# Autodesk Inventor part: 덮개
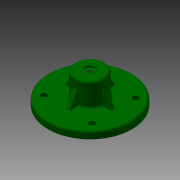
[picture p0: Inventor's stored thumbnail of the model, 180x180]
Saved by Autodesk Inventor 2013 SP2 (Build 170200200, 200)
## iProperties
Created: 2017-08
Part Number: 덮개
Material: 알루미늄 6061
Document SubType Name: Modeling
Designer: mduedu
Density: 2.71 g/cm^3
Mass: 358.12 g
Surface Area: 294.002 cm^2
Volume: 132.148 cm^3
Author: mduedu
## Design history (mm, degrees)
sketch "스케치1"
  geometry: C1 r 57.5 at (0, 0); 1 further point
  constraints: 1 centre point, 1 coincident
  dimensions: "d69" = 115 diameter of C1
extrude "돌출1" new body sketch "스케치1" distance "d5" = 10; taper "d6" = 0 deg
sketch "스케치2"
  geometry: C1 r 20 at (0, 0); 1 further point
  constraints: 1 centre point, 1 coincident
  dimensions: "d55" = 40 diameter of C1
extrude "돌출2" join sketch "스케치2" distance "d9" = 32; taper "d10" = 0 deg
sketch "스케치3"
  geometry: L1 (-26, -26)-(26, -26); L2 (26, -26)-(26, 26); L3 (26, 26)-(-26, 26); L4 (-26, 26)-(-26, -26); L5 (-26, -26)-(26, 26); L6 (26, -26)-(-26, 26); 1 further point
  constraints: 12 end point, 2 midpoint, 2 parallel, 2 perpendicular, 1 horizontal
  dimensions: "d11" = 52 distance of L3.end L2.end
extrude "돌출3" join sketch "스케치3" distance "d12" = 6; taper "d13" = 0 deg
sketch "스케치4"
  geometry: L1 (-17, -17)-(17, -17); L2 (17, -17)-(17, 17); L3 (17, 17)-(-17, 17); L4 (-17, 17)-(-17, -17); L5 (-17, -17)-(17, 17); L6 (17, -17)-(-17, 17); 1 further point
  constraints: 12 end point, 2 midpoint, 2 parallel, 2 perpendicular, 1 horizontal
  dimensions: "d14" = 34 distance of L2.end L3.end
extrude "돌출4" cut sketch "스케치4" distance "d16" = 5; taper "d17" = 0 deg
sketch "스케치5"
  geometry: C1 r 9 at (0, 0); 1 further point
  constraints: 1 centre point, 1 coincident
  dimensions: "d18" = 18 diameter of C1
extrude "돌출5" cut sketch "스케치5" distance "d19" = 34; taper "d20" = 0 deg
sketch "스케치6"
  geometry: 2 further points
  constraints: 1 coincident
hole "구멍1" sketch "스케치6" at (0, 0) diameter "d21" = 5.917; stored, may be unused: countersink angle "d25" = 90 deg, drill point angle "d27" = 118 deg; dims "d22" = 6, "d23" = 14, "d24" = 2, "d26" = 8
fillet "모깎기3" dims "d38" = 3
fillet "모깎기4" dims "d39" = 3
fillet "모깎기5" dims "d40" = 3
chamfer "모따기2" distance "d70" = 6; stored, may be unused: second distance "d71" = 2, angle "d72" = 45 deg
chamfer "모따기1" distance "d41" = 1; stored, may be unused: second distance "d42" = 2, angle "d43" = 45 deg
fillet "모깎기6" dims "d44" = 3
fillet "모깎기7" dims "d45" = 3
fillet "모깎기8" dims "d46" = 3
sketch "스케치9"
  geometry: L1 (-33, -30)-(33, -30); L2 (33, -30)-(33, 30); L3 (33, 30)-(-33, 30); L4 (-33, 30)-(-33, -30); L5 (-33, -30)-(33, 30); L6 (33, -30)-(-33, 30); C1 r 54.5 at (0, 0) reference; 3 further points
  constraints: 12 end point, 2 coincident, 2 midpoint, 2 parallel, 2 point on line, 1 horizontal, 1 perpendicular
  dimensions: "d77" = 66 distance of L2.end L3.end; "d79" = 60 distance of L1.end L2.end
hole "구멍3" sketch "스케치9" at (-33, -30), (-33, 30), (33, 30), (33, -30) diameter "d48" = 4.5; stored, may be unused: countersink angle "d52" = 90 deg, drill point angle "d54" = 0 deg; dims "d49" = 6, "d50" = 8, "d51" = 4.6, "d53" = 8
sketch "스케치10"
  geometry: L1 (-7, 40)-(-2.958, 40) reference; L2 (-2.958, 40)-(-2.958, 33) reference; L3 (-2.958, 33)-(-6, 33) reference; L4 (-9, 30)-(-9, -1) reference; L5 (-9, -1)-(-14, -1) reference; L6 (-17, -4)-(-17, -6) reference; L7 (-17, -6)-(-25, -6) reference; L8 (-25, -6)-(-26, -5) reference; L9 (-26, -5)-(-26, 0) reference; L10 (-26, 0)-(-57.5, 0) reference; L11 (-54.5, 10)-(-23, 10) reference; L12 (-20, 13)-(-20, 39) reference; L13 (-17, 42)-(-7, 42) reference; L14 (-7, 42)-(-7, 40) reference; L15 (2.958, 40)-(7, 40) reference; L16 (7, 40)-(7, 42) reference; L17 (7, 42)-(17, 42) reference; L18 (20, 39)-(20, 13) reference; L19 (23, 10)-(54.5, 10) reference; L20 (57.5, 0)-(26, 0) reference; L21 (26, 0)-(26, -5) reference; L22 (26, -5)-(25, -6) reference; L23 (25, -6)-(17, -6) reference; L24 (17, -6)-(17, -4) reference; L25 (14, -1)-(9, -1) reference; L26 (9, -1)-(9, 30) reference; L27 (6, 33)-(2.958, 33) reference; L28 (2.958, 33)-(2.958, 40) reference; L29 (31.547, 10)-(20, 30); L30 (-57.5, 0)-(-57.5, 7) reference; L31 (57.5, 7)-(57.5, 0) reference; A1 r 3 centre (-6, 30) between (-6, 33) and (-9, 30) reference; A2 r 3 centre (-14, -4) between (-14, -1) and (-17, -4) reference; A3 r 3 centre (-23, 13) between (-23, 10) and (-20, 13) reference; A4 r 3 centre (-17, 39) between (-17, 42) and (-20, 39) reference; A5 r 3 centre (17, 39) between (20, 39) and (17, 42) reference; A6 r 3 centre (23, 13) between (20, 13) and (23, 10) reference; A7 r 3 centre (14, -4) between (17, -4) and (14, -1) reference; A8 r 3 centre (6, 30) between (9, 30) and (6, 33) reference; A9 r 3 centre (-54.5, 7) between (-54.5, 10) and (-57.5, 7) reference; 2 further points
  constraints: 2 end point, 2 point on line, 1 other
  dimensions: "d56" = 20 distance from line of L29.end L19; "d57" = 120 deg angle of L29 L19
feature "리브1" sketch "스케치10" dims "d58" = 1, "d59" = 6, "d60" = 0, "d61" = 0, "d62" = 1, "d63" = 1
fillet "모깎기9" dims "d64" = 1
fillet "모깎기10" dims "d65" = 1
node "솔리드1"
pattern_circular "원형 패턴1" dims "d67" = 360 deg
node "절단 모서리 투영1"
